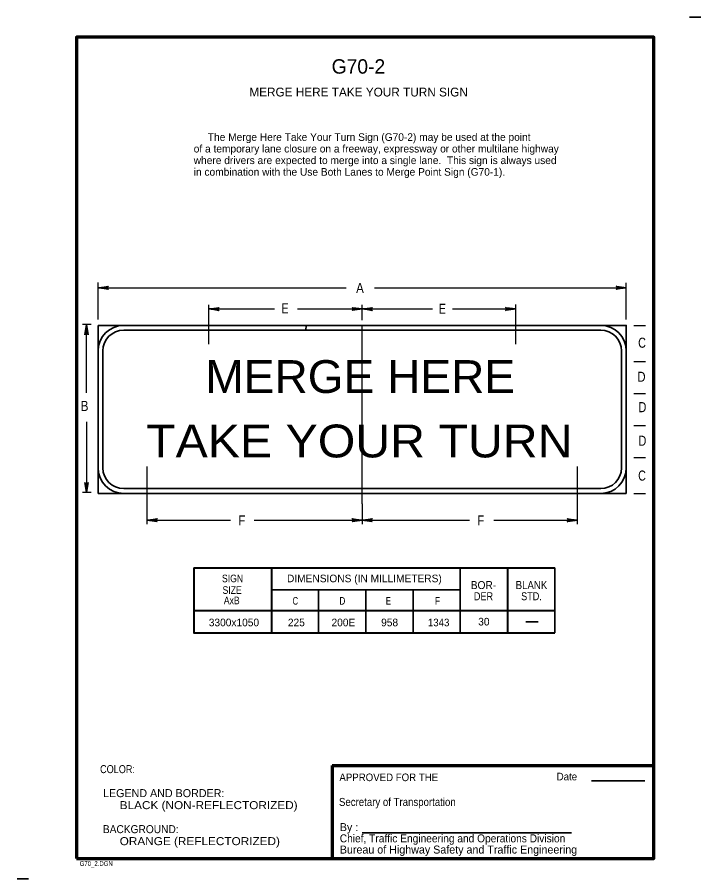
# Model space of a CAD drawing. Extents: x 0.165 to 0.379, y -32.602 to -32.333.
import ezdxf
from ezdxf.enums import TextEntityAlignment as Align

# ---------------------------------------------------------------- set-up
doc = ezdxf.new("R2010")
doc.units = 0
doc.header["$LTSCALE"] = 0.00095
doc.linetypes.add('DOT_DASHED', pattern=[7.7, 5, -1.2, 0.3, -1.2])
doc.layers.add('1', color=7, linetype='Continuous', lineweight=25)
doc.layers.add('3', color=7, linetype='Continuous', lineweight=35)

msp = doc.modelspace()

# ---------------------------------------------------------------- linework, layer by layer
at = {"layer": '1', "lineweight": 35}
for p, q in [((0.378625, -32.333125), (0.375125, -32.333125)), ((0.190375, -32.429375), (0.198375, -32.429375)), ((0.190375, -32.429375), (0.190375, -32.437375)), ((0.198375, -32.429375), (0.255375, -32.429375)), ((0.190375, -32.473875), (0.190375, -32.437375)), ((0.191875, -32.437375), (0.191875, -32.473875)), ((0.353875, -32.473875), (0.353875, -32.437375)), ((0.355375, -32.437375), (0.355375, -32.473875)), ((0.190375, -32.473875), (0.190375, -32.481875)), ((0.355375, -32.473875), (0.355375, -32.481875)), ((0.198375, -32.480375), (0.347375, -32.480375)), ((0.190375, -32.481875), (0.198375, -32.481875)), ((0.347375, -32.481875), (0.198375, -32.481875)), ((0.347375, -32.481875), (0.355375, -32.481875)), ((0.3445, -32.571625), (0.361125, -32.571625)), ((0.272875, -32.587875), (0.33825, -32.587875)), ((0.168625, -32.60225), (0.165125, -32.60225))]:
    msp.add_line(p, q, dxfattribs=at)
at = {"layer": '1'}
for p, q in [((0.190375, -32.4275), (0.190375, -32.416)), ((0.190375, -32.417625), (0.267875, -32.417625)), ((0.27675, -32.417625), (0.355375, -32.417625)), ((0.355375, -32.4275), (0.355375, -32.416125)), ((0.225, -32.43525), (0.225, -32.423)), ((0.272875, -32.42775), (0.272875, -32.423)), ((0.320875, -32.43525), (0.320875, -32.422875)), ((0.225, -32.42425), (0.2455, -32.42425)), ((0.301125, -32.42425), (0.320875, -32.42425)), ((0.18825, -32.429125), (0.1855, -32.429125)), ((0.18675, -32.4505), (0.18675, -32.429125)), ((0.35775, -32.429375), (0.361375, -32.429375)), ((0.35775, -32.440625), (0.361375, -32.440625)), ((0.35775, -32.450625), (0.361375, -32.450625)), ((0.18675, -32.4595), (0.18675, -32.481625)), ((0.35775, -32.460625), (0.361375, -32.460625)), ((0.35775, -32.470625), (0.361375, -32.470625)), ((0.20575, -32.4915), (0.20575, -32.4735)), ((0.340125, -32.4915), (0.340125, -32.4735)), ((0.18825, -32.481625), (0.1855, -32.481625)), ((0.35775, -32.481875), (0.361375, -32.481875)), ((0.272875, -32.485125), (0.272875, -32.4915)), ((0.20575, -32.49025), (0.23175, -32.49025)), ((0.314, -32.49025), (0.340125, -32.49025))]:
    msp.add_line(p, q, dxfattribs=at)
at = {"layer": '1', "linetype": 'DOT_DASHED'}
msp.add_line((0.272875, -32.485125), (0.272875, -32.429375), dxfattribs=at)
at = {"layer": '1', "lineweight": 70}
for q in [(0.364, -32.566875), (0.2635, -32.595875)]:
    msp.add_line((0.2635, -32.566875), q, dxfattribs=at)
msp.add_lwpolyline([(0.183625, -32.595875), (0.364, -32.595875), (0.364, -32.339375), (0.183625, -32.339375)], close=True, dxfattribs=at)
at = {"layer": '1'}
for points in [[(0.193375, -32.418), (0.19325, -32.417875), (0.190375, -32.417625), (0.193375, -32.418), (0.1935, -32.418125), (0.190375, -32.417625), (0.19325, -32.4175), (0.193375, -32.417375), (0.190375, -32.417625), (0.1935, -32.417125), (0.193375, -32.417375)], [(0.352375, -32.41725), (0.3525, -32.4175), (0.355375, -32.417625), (0.352375, -32.41725), (0.35225, -32.417125), (0.355375, -32.417625), (0.3525, -32.417875), (0.352375, -32.418), (0.355375, -32.417625), (0.35225, -32.418125), (0.352375, -32.418)], [(0.228, -32.424625), (0.227875, -32.4245), (0.225, -32.42425), (0.228, -32.424625), (0.228125, -32.424875), (0.225, -32.42425), (0.227875, -32.424125), (0.228, -32.424), (0.225, -32.42425), (0.228125, -32.42375), (0.228, -32.424)], [(0.269875, -32.423875), (0.27, -32.424125), (0.272875, -32.42425), (0.269875, -32.423875), (0.26975, -32.42375), (0.272875, -32.42425), (0.27, -32.4245), (0.269875, -32.424625), (0.272875, -32.42425), (0.26975, -32.42475), (0.269875, -32.424625)], [(0.275875, -32.424625), (0.27575, -32.4245), (0.272875, -32.42425), (0.275875, -32.424625), (0.276, -32.424875), (0.272875, -32.42425), (0.27575, -32.424125), (0.275875, -32.424), (0.272875, -32.42425), (0.276, -32.42375), (0.275875, -32.424)], [(0.317875, -32.423875), (0.317875, -32.424125), (0.320875, -32.42425), (0.317875, -32.423875), (0.317625, -32.42375), (0.320875, -32.42425), (0.317875, -32.4245), (0.317875, -32.424625), (0.320875, -32.42425), (0.317625, -32.42475), (0.317875, -32.424625)], [(0.252625, -32.42425), (0.272875, -32.42425), (0.294875, -32.42425)], [(0.186375, -32.432125), (0.186625, -32.432), (0.18675, -32.429125), (0.186375, -32.432125), (0.18625, -32.432375), (0.18675, -32.429125), (0.186875, -32.432), (0.187125, -32.432125), (0.18675, -32.429125), (0.18725, -32.432375), (0.187125, -32.432125)], [(0.187125, -32.478625), (0.186875, -32.47875), (0.18675, -32.481625), (0.187125, -32.478625), (0.18725, -32.4785), (0.18675, -32.481625), (0.186625, -32.47875), (0.186375, -32.478625), (0.18675, -32.481625), (0.18625, -32.4785), (0.186375, -32.478625)], [(0.20875, -32.490625), (0.208625, -32.490375), (0.20575, -32.49025), (0.20875, -32.490625), (0.208875, -32.49075), (0.20575, -32.49025), (0.208625, -32.490125), (0.20875, -32.489875), (0.20575, -32.49025), (0.208875, -32.48975), (0.20875, -32.489875)], [(0.239125, -32.49025), (0.272875, -32.49025), (0.306375, -32.49025)], [(0.269875, -32.489875), (0.27, -32.490125), (0.272875, -32.49025), (0.269875, -32.489875), (0.26975, -32.48975), (0.272875, -32.49025), (0.27, -32.490375), (0.269875, -32.490625), (0.272875, -32.49025), (0.26975, -32.49075), (0.269875, -32.490625)], [(0.275875, -32.490625), (0.27575, -32.490375), (0.272875, -32.49025), (0.275875, -32.490625), (0.276, -32.49075), (0.272875, -32.49025), (0.27575, -32.490125), (0.275875, -32.489875), (0.272875, -32.49025), (0.276, -32.48975), (0.275875, -32.489875)], [(0.337125, -32.489875), (0.337125, -32.490125), (0.340125, -32.49025), (0.337125, -32.489875), (0.336875, -32.48975), (0.340125, -32.49025), (0.337125, -32.490375), (0.337125, -32.490625), (0.340125, -32.49025), (0.336875, -32.49075), (0.337125, -32.490625)]]:
    msp.add_lwpolyline(points, dxfattribs=at)
at = {"layer": '1', "lineweight": 35}
for points in [[(0.255375, -32.429375), (0.25525, -32.430875), (0.198375, -32.430875)], [(0.347375, -32.430875), (0.25525, -32.430875), (0.255375, -32.429375), (0.347375, -32.429375)], [(0.347375, -32.429375), (0.355375, -32.429375), (0.355375, -32.437375)]]:
    msp.add_lwpolyline(points, dxfattribs=at)
for centre, radius, start, end in [((0.198375, -32.437375), 0.008, 90, 180), ((0.347375, -32.437375), 0.008, 0, 90), ((0.198375, -32.437375), 0.0065, 90, 180), ((0.347375, -32.437375), 0.0065, 0, 90), ((0.198375, -32.473875), 0.008, 180, 270), ((0.198375, -32.473875), 0.0065, 180, 270), ((0.347375, -32.473875), 0.0065, 270, 0), ((0.347375, -32.473875), 0.008, 270, 0)]:
    msp.add_arc(centre, radius, start, end, dxfattribs=at)
at = {"layer": '3', "lineweight": 40}
for p, q in [((0.22025, -32.505125), (0.333, -32.505125)), ((0.2445, -32.505125), (0.2445, -32.525375)), ((0.31825, -32.505125), (0.31825, -32.525375)), ((0.22025, -32.5185), (0.333, -32.5185))]:
    msp.add_line(p, q, dxfattribs=at)
at = {"layer": '3'}
for p, q in [((0.3035, -32.505125), (0.3035, -32.525375)), ((0.333, -32.505125), (0.333, -32.525375)), ((0.3035, -32.512), (0.2445, -32.512)), ((0.25925, -32.512), (0.25925, -32.525375)), ((0.274, -32.512), (0.274, -32.525375)), ((0.28875, -32.512), (0.28875, -32.525375)), ((0.324, -32.522), (0.327875, -32.522))]:
    msp.add_line(p, q, dxfattribs=at)
at = {"layer": '3', "lineweight": 40}
msp.add_lwpolyline([(0.22025, -32.505125), (0.22025, -32.525375), (0.333, -32.525375)], dxfattribs=at)

# ---------------------------------------------------------------- texts
at = {"layer": '1'}
for s, height, p in [('G70-2', 0.0045, (0.271688, -32.35075)), ('MERGE HERE TAKE YOUR TURN SIGN', 0.00275, (0.27175, -32.357875))]:
    msp.add_text(s, height=height, dxfattribs=at).set_placement(p, align=Align.CENTER)
for s, height, p in [('     The Merge Here Take Your Turn Sign (G70-2) may be used at the point', 0.002375, (0.22025, -32.37175)), ('of a temporary lane closure on a freeway, expressway or other multilane highway', 0.002375, (0.22025, -32.375375)), ('where drivers are expected to merge into a single lane.  This sign is always used', 0.002375, (0.22025, -32.379)), ('in combination with the Use Both Lanes to Merge Point Sign (G70-1).', 0.002375, (0.22025, -32.382625)), (' LEGEND AND BORDER:', 0.0025, (0.191, -32.57675)), ('By :', 0.0025, (0.265875, -32.587375)), ('Bureau of Highway Safety and Traffic Engineering', 0.0025, (0.265875, -32.594375))]:
    msp.add_text(s, height=height, dxfattribs=at).set_placement(p)
for s, height, width, p in [('A', 0.00315, 0.85, (0.273375, -32.41925)), ('E', 0.003125, 0.8, (0.249875, -32.425625)), ('E', 0.003125, 0.8, (0.299, -32.42575)), ('C', 0.00315, 0.8, (0.3615, -32.436375)), ('D', 0.003125, 0.85, (0.361375, -32.447)), ('B', 0.00315, 0.85, (0.187375, -32.456125)), ('D', 0.00315, 0.8, (0.361625, -32.4565)), ('D', 0.00315, 0.8, (0.361625, -32.467)), ('C', 0.00315, 0.8, (0.3615, -32.477875)), ('F', 0.003125, 0.85, (0.236375, -32.491875)), ('F', 0.003125, 0.85, (0.311, -32.491875))]:
    msp.add_text(s, height=height, dxfattribs=dict(at, width=width)).set_placement(p, align=Align.RIGHT)
for s, height, width, p in [('MERGE HERE', 0.01025, 1.05, (0.223875, -32.4505)), ('TAKE YOUR TURN', 0.01025, 1.1, (0.205375, -32.470625)), ('COLOR:', 0.0025, 0.85, (0.191, -32.56925)), ('APPROVED FOR THE', 0.002375, 0.95, (0.26575, -32.57175)), ('Date ', 0.002375, 0.95, (0.333625, -32.5715)), ('Secretary of Transportation', 0.0025, 0.9, (0.265625, -32.5795)), ('      BLACK (NON-REFLECTORIZED)', 0.0025, 1.1, (0.191, -32.5805)), (' BACKGROUND:', 0.0025, 0.95, (0.191, -32.588)), ('Chief, Traffic Engineering and Operations Division', 0.0025, 0.95, (0.265875, -32.590875)), ('      ORANGE (REFLECTORIZED)', 0.0025, 1.1, (0.191, -32.59175)), ('G70_2.DGN', 0.0015, 0.75, (0.184625, -32.59825))]:
    msp.add_text(s, height=height, dxfattribs=dict(at, width=width)).set_placement(p)
at = {"layer": '3'}
for s, height, width, p in [('SIGN', 0.002375, 0.85, (0.232375, -32.509625)), ('BOR-', 0.0025, 0.95, (0.31075, -32.51175)), ('BLANK', 0.0025, 0.9, (0.32575, -32.51175)), ('SIZE', 0.002375, 0.85, (0.23225, -32.51325)), ('DER', 0.0025, 0.85, (0.31075, -32.51525)), ('STD.', 0.0025, 0.85, (0.32575, -32.51525)), ('AxB', 0.002375, 0.85, (0.232125, -32.5165)), ('C', 0.002375, 0.75, (0.252, -32.516625)), ('D', 0.002375, 0.8, (0.266688, -32.516625)), ('E', 0.002375, 0.75, (0.281062, -32.516625)), ('F', 0.002375, 0.8, (0.296375, -32.516625)), ('1343', 0.002375, 0.95, (0.29675, -32.523375))]:
    msp.add_text(s, height=height, dxfattribs=dict(at, width=width)).set_placement(p, align=Align.CENTER)
for s, p in [('DIMENSIONS (IN MILLIMETERS)', (0.273562, -32.509625)), ('3300x1050', (0.232813, -32.523375)), ('225', (0.252312, -32.523375)), ('200E', (0.267, -32.523375)), ('958', (0.281438, -32.523375)), ('30', (0.310875, -32.523125))]:
    msp.add_text(s, height=0.002375, dxfattribs=at).set_placement(p, align=Align.CENTER)

doc.saveas('drawing.dxf')
